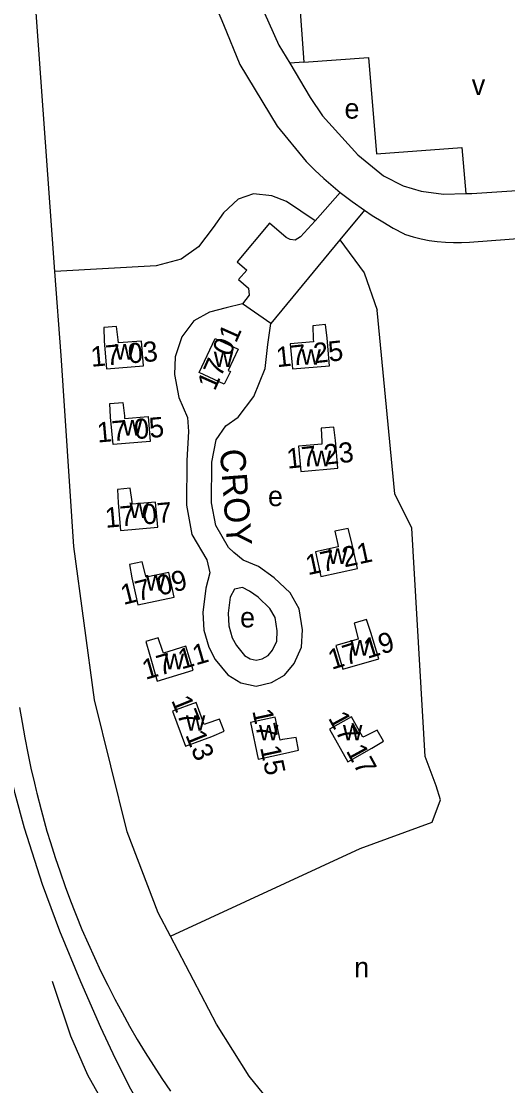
# Model space of a CAD drawing. Extents: x 157794 to 159375, y 380877 to 382306.
# Drawn here: x 157944 to 158040.7, y 381049.1 to 381260.8 of the extents above; entities that cross this region are included whole.
import ezdxf

# ---------------------------------------------------------------- set-up
doc = ezdxf.new("R2010")
doc.units = 0
for name, color, linetype in [('BLT_Basislijn', 7, 'Continuous'), ('BLT_Bebouwing', 7, 'Continuous'), ('BLT_Centroide', 7, 'Continuous'), ('BLT_Huisnummer', 7, 'Continuous'), ('BLT_Straatnaam', 7, 'Continuous')]:
    doc.layers.add(name, color=color, linetype=linetype)

msp = doc.modelspace()

# ---------------------------------------------------------------- linework, layer by layer
at = {"layer": 'BLT_Basislijn'}
for p, q in [((157997.68, 381285.99), (158000.17, 381252.63)), ((158000.17, 381252.63), (157997.35, 381252.43)), ((158033.61, 381226.55), (158050, 381227.68)), ((158032.38, 381226.51), (158033.61, 381226.55)), ((158012.21, 381223.21), (158007.33, 381217.3)), ((158020.21, 381218.48), (158020.39, 381218.38)), ((158007.33, 381217.3), (157993.61, 381200.68))]:
    msp.add_line(p, q, dxfattribs=at)
for points in [[(157975.88, 381303.19), (157977.67, 381283.7), (157979.73, 381273.14), (157981.67, 381266.17), (157984.15, 381260.12)], [(157950.66, 381211.02), (157945.55, 381281.8), (157946.65, 381284.77), (157949.06, 381286.82), (157961.87, 381295.03)], [(157986.21, 381289.71), (157987.72, 381277.21), (157991.22, 381264.9), (157995.18, 381256.07), (157997.35, 381252.43)], [(157984.15, 381260.12), (157987.4, 381252.17), (157994.88, 381239.92), (158000.64, 381232.92)], [(157997.35, 381252.43), (158001.4, 381245.6)], [(158000.17, 381252.63), (158013.03, 381253.57)], [(158013.03, 381253.57), (158014.62, 381234.41), (158031.62, 381235.72), (158032.38, 381226.51)], [(158001.4, 381245.6), (158003.87, 381241.98), (158010.93, 381234.25), (158016.04, 381230.05), (158019.95, 381228.08), (158023.52, 381227), (158027.91, 381226.39), (158032.38, 381226.51)], [(158000.64, 381232.92), (158002.36, 381231.21), (158004.14, 381229.54), (158005.97, 381227.94), (158007.39, 381226.77)], [(158002.39, 381221.14), (157996.74, 381224.97), (157993.79, 381226.09), (157990.16, 381226.48), (157987.09, 381225.39), (157984.21, 381222.68), (157982.11, 381219.75), (157979.24, 381215.95), (157975.78, 381213.46), (157970.76, 381212.19), (157950.66, 381211.02)], [(158007.39, 381226.77), (158002.39, 381221.14)], [(158007.39, 381226.77), (158009.78, 381224.93), (158012.21, 381223.21)], [(158012.21, 381223.21), (158013.78, 381222.16), (158015.85, 381220.88), (158017.95, 381219.67), (158020.1, 381218.53), (158020.21, 381218.48)], [(158002.39, 381221.14), (157999.53, 381217.92), (157998.43, 381217.28), (157997.42, 381217.41), (157996.67, 381217.82), (157993.32, 381220.63), (157986.87, 381212.96), (157988.79, 381211.33), (157987.15, 381209.43), (157989.17, 381207.74), (157989.32, 381206.32), (157989.32, 381206.32), (157987.98, 381204.61)], [(158007.33, 381217.3), (158012.15, 381210.74), (158014.72, 381203.34)], [(158020.39, 381218.38), (158021.94, 381217.92), (158023.51, 381217.53), (158025.1, 381217.23), (158026.7, 381216.99), (158028.31, 381216.85), (158029.93, 381216.77), (158031.54, 381216.78), (158033.14, 381216.87)], [(158033.14, 381216.87), (158048.04, 381218.01), (158050, 381216.26)], [(157973.65, 381078.85), (157971.21, 381083.51), (157965.02, 381099.64), (157958.51, 381125.88), (157954.43, 381156.35), (157951.86, 381194.34), (157950.66, 381211.02)], [(157987.98, 381204.61), (157984.74, 381203.82), (157981.37, 381202.95), (157978.25, 381201.22), (157975.91, 381198.05), (157974.55, 381194.09), (157974.45, 381190.54), (157975.31, 381186.01), (157977, 381181.99), (157977.21, 381179.2), (157976.88, 381173.48), (157976.8, 381164.55), (157977.9, 381158.74), (157980.84, 381153.67), (157981.45, 381151.11), (157980.67, 381148.05), (157980.1, 381143.23), (157980.3, 381139.74), (157981.25, 381136.34), (157982.54, 381133.87), (157985.05, 381130.82), (157987.64, 381129.27), (157990.71, 381128.61), (157993.73, 381129.31), (157996.33, 381130.78), (157998.24, 381133.06), (157999.7, 381136.32), (157999.9, 381139.81), (157999.24, 381143.96), (157997.41, 381147.12), (157994.29, 381150.13), (157991.14, 381152.39), (157988.08, 381153.63), (157986.26, 381155.15), (157985.17, 381156.17), (157982.66, 381160.51), (157981.81, 381165), (157981.88, 381173.15), (157982.7, 381177.58), (157984.65, 381180.37), (157987.12, 381182.1), (157990.24, 381186.19), (157992.44, 381191.72), (157992.99, 381196.49), (157993.61, 381200.68)], [(157993.61, 381200.68), (157987.98, 381204.61)], [(157973.65, 381078.85), (158011.37, 381096.31), (158025.72, 381101.56), (158027.36, 381105.99), (158026.46, 381108.78), (158024.32, 381114.57), (158021.65, 381160.01), (158018.24, 381166.8), (158014.72, 381203.34)], [(157955.82, 381069.77), (157951.64, 381079.87), (157948.21, 381089.13), (157944.6, 381100.37), (157942.75, 381107.14), (157940.84, 381115.66), (157938.98, 381126.08), (157937.64, 381135.68), (157936.03, 381150.24), (157934.94, 381160.71)], [(157986.39, 381147.86), (157985.5, 381146.27), (157985.12, 381143.08), (157985.26, 381140.57), (157985.93, 381138.19), (157986.74, 381136.64), (157988.36, 381134.67), (157989.5, 381133.99), (157990.67, 381133.74), (157991.9, 381134.02), (157993.08, 381134.69), (157993.96, 381135.74), (157994.76, 381137.53), (157994.88, 381139.56), (157994.45, 381142.26), (157993.43, 381144.01), (157991.08, 381146.28), (157989.37, 381147.5), (157987.95, 381148.19), (157986.39, 381147.86)], [(157943.6, 381124.36), (157944.12, 381121.32), (157944.67, 381118.29), (157945.26, 381115.27), (157945.89, 381112.27), (157946.57, 381109.28), (157946.91, 381107.85), (157947.05, 381107.3), (157947.89, 381104), (157948.8, 381100.72), (157949.07, 381099.77), (157949.76, 381097.46), (157950.68, 381094.54), (157951.66, 381091.64), (157952.68, 381088.76), (157953.74, 381085.89), (157954.6, 381083.7), (157954.86, 381083.04), (157956.03, 381080.21), (157957.24, 381077.4), (157958.5, 381074.61), (157959.81, 381071.84), (157961.16, 381069.09), (157962.56, 381066.37), (157964, 381063.67), (157965.5, 381061), (157967.03, 381058.35), (157968.61, 381055.73), (157970.24, 381053.14), (157971.9, 381050.57), (157973.61, 381048.03)], [(158052.05, 380932.59), (158049.41, 380933.42), (158042.83, 380943.01), (158039.05, 380949.16), (158037.6, 380952.96), (158035.52, 380959.89), (158033.42, 380971.12), (158028.68, 380990.05), (158025.05, 381000.76), (158020.21, 381013.7), (158017.15, 381019.44), (158008.21, 381029.22), (157998.71, 381039.46), (157989.31, 381051.01), (157982.79, 381061.35), (157973.65, 381078.85)], [(157950.1, 381069.92), (157953.72, 381059.06), (157957.14, 381051.29), (157965.28, 381036.75), (157974.51, 381024.02)], [(158017.24, 380934.18), (158016.26, 380945.71), (158015.56, 380951.31), (158014.9, 380957.53), (158014.29, 380961.55), (158012.98, 380969.48), (158012.16, 380973.56), (158011.16, 380977.77), (158009.98, 380981.76), (158008.87, 380985.41), (158006.86, 380990.14), (158005.41, 380993.34), (158003.6, 380996.76), (157999.88, 381002.75), (157995.33, 381009.1), (157990.25, 381015.55), (157983.03, 381024.26), (157977.37, 381031.08), (157972.45, 381037.64), (157968.85, 381042.93), (157965.73, 381048.44), (157962.67, 381054.47), (157959.76, 381060.71), (157955.82, 381069.77)]]:
    msp.add_lwpolyline(points, dxfattribs=at)
at = {"layer": 'BLT_Bebouwing'}
for points in [[(157967.89, 381197.19), (157963.28, 381196.83), (157963.23, 381197.43), (157962.91, 381200.08), (157960.36, 381199.88), (157960.47, 381197.21), (157960.9, 381191.71), (157968.28, 381192.29)], [(158004.83, 381197.8), (158004.5, 381200.47), (158001.94, 381200.25), (158002.05, 381197.57), (158002.1, 381197.06), (157997.46, 381196.63), (157997.93, 381191.68), (158005.29, 381192.3)], [(157982.51, 381197.7), (157987.07, 381195.57), (157985.1, 381191.36), (157985.58, 381191.13), (157984.33, 381188.64), (157979.36, 381190.97)], [(157961.72, 381182.1), (157961.59, 381184.77), (157964.15, 381185), (157964.49, 381182.35), (157964.52, 381181.81), (157969.19, 381182.2), (157969.6, 381177.26), (157962.21, 381176.6)], [(158006.48, 381177.4), (158006.16, 381180.06), (158003.6, 381179.85), (158003.71, 381177.17), (158003.75, 381176.68), (157999.12, 381176.27), (157999.57, 381171.28), (158006.94, 381171.9)], [(157965.99, 381165.26), (157965.64, 381167.92), (157963.09, 381167.7), (157963.21, 381165.02), (157963.7, 381159.52), (157971.1, 381160.17), (157970.66, 381165.16), (157966.03, 381164.75)], [(158009.65, 381157.35), (158008.96, 381159.94), (158006.34, 381159.37), (158006.91, 381156.75), (158007.02, 381156.26), (158002.49, 381155.29), (158003.54, 381150.39), (158010.81, 381151.95)], [(157968.67, 381150.71), (157967.99, 381153.29), (157965.49, 381152.75), (157965.95, 381150.11), (157967.12, 381144.72), (157974.38, 381146.29), (157973.31, 381151.21), (157968.77, 381150.22)], [(158013.46, 381139.28), (158012.62, 381141.82), (158010.16, 381141.1), (158010.81, 381138.5), (158010.98, 381137.95), (158006.52, 381136.69), (158007.92, 381131.93), (158015.05, 381134.02)], [(157972.08, 381135.7), (157971.19, 381138.2), (157968.75, 381137.48), (157969.45, 381134.92), (157971.01, 381129.59), (157978.13, 381131.74), (157976.67, 381136.55), (157972.25, 381135.16)], [(157978.77, 381125.34), (157974.06, 381123.59), (157976.64, 381116.62), (157981.85, 381118.6), (157984.32, 381119.64), (157983.4, 381122.03), (157980.86, 381121.18), (157980.31, 381120.97)], [(157994.45, 381122.39), (157989.55, 381121.33), (157991.11, 381114.07), (157996.51, 381115.23), (157999.11, 381115.87), (157998.62, 381118.37), (157995.95, 381117.96), (157995.43, 381117.84)], [(158009.66, 381122.47), (158005.29, 381120.05), (158008.89, 381113.55), (158013.72, 381116.23), (158016.01, 381117.61), (158014.77, 381119.86), (158012.37, 381118.66), (158011.92, 381118.41)]]:
    msp.add_lwpolyline(points, close=True, dxfattribs=at)

# ---------------------------------------------------------------- texts
at = {"layer": 'BLT_Centroide'}
for s, p in [('v', (158033.57, 381246.16)), ('e', (158008.25, 381241.43)), ('w', (157962.6, 381193.52)), ('w', (157999.68, 381192.5)), ('w', (157982.25, 381192.04)), ('w', (157964.13, 381178.4)), ('w', (158001.75, 381172.32)), ('e', (157993.03, 381164.37)), ('w', (157965.47, 381162.02)), ('w', (158004.96, 381152.9)), ('w', (157968.75, 381147.59)), ('e', (157987.48, 381140.26)), ('w', (158009.4, 381134.66)), ('w', (157972.47, 381131.95)), ('w', (157976.7, 381119.71)), ('w', (157991.24, 381117.78)), ('w', (158007.94, 381117.78)), ('n', (158010.19, 381070.66))]:
    msp.add_text(s, height=4, dxfattribs=at).set_placement(p)
at = {"layer": 'BLT_Huisnummer'}
for s, rotation, p in [('17 01', 66.0638, (157982.45, 381187.15)), ('17 25', 6.0638, (157994.85, 381191.99)), ('17 03', 5.0638, (157957.93, 381192.07)), ('17 05', 5.0638, (157959.17, 381177.01)), ('17 23', 6.0638, (157996.93, 381171.81)), ('17 07', 5.0638, (157960.75, 381160.05)), ('17 21', 12.0638, (158000.97, 381150.63)), ('17 09', 14.0638, (157964.27, 381144.71)), ('17 19', 17.0638, (158005.71, 381131.81)), ('17 11', 16.0638, (157968.67, 381129.82)), ('17 13', 292.0638, (157973.74, 381125.78)), ('17 15', 282.0638, (157989.89, 381123.67)), ('17 17', 298.5638, (158004.92, 381122.25))]:
    msp.add_text(s, height=4, rotation=rotation, dxfattribs=at).set_placement(p)
at = {"layer": 'BLT_Straatnaam'}
msp.add_text('CROY', height=5, rotation=274.309, dxfattribs=at).set_placement((157983.45, 381175.59))

doc.saveas('drawing.dxf')
